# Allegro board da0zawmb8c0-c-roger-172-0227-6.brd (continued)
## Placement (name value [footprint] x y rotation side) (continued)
C6616  180p/50V_4  [C0402]  54.8 103.11 270 top
C6617  *15p/50V_4  [C0402]  66.79 26.48 180 bottom
C6618  0.1u/6.3V_2  [C0201]  172.58 19.95 0 top
C6619  0.1u/6.3V_2  [C0201]  100.9 60.44 180 bottom
C6620  0.1u/6.3V_2  [C0201]  102.98 37.43 90 top
C6622  0.1u/6.3V_2  [C0201]  103.39 30.69 90 bottom
C6623  0.1u/6.3V_2  [C0201]  87.69 49.29 90 top
C6624  0.1u/25V_4  [C0402]  60.03 107.1 0 top
C6625  1000p/50V_4  [C0402]  60.03 106.13 0 top
C6626  *0.1u/16V_2  [C0201]  71.44 32.12 180 bottom
C20000  0.1u/16V_4  [C0402]  45.27 114.54 180 top
C20001  180p/50V_4  [C0402]  56.2 103.82 270 bottom
C20002  180p/50V_4  [C0402]  57.19 104.79 270 bottom
CN1  50281-00201-001  [50281-00201-001-2P-L]  14.3 3.45 180 bottom
CN2  USB3.0 CONN  [UB3-10580-09001-9P]  7.4 54.44 90 bottom
CN3  USB3.0 CONN  [UB3-10580-09001-9P]  7.4 34.44 90 bottom
CN8  2RJ1622-001111F  [RJ45-2RJ1622-001111F-8P]  10.05 96.2 90 bottom
CN10  TPC@USB3.1  [UB31-C12321-1242D-L-24P]  1.46 15.9 90 bottom
CN13  KBL@50505-00401-v01-4p-l  [50505-00401-V01-4P-L]  204.32 10.95 180 bottom
CN14  PBA@196241-08021-3  [196241-08021-3-8P-L]  58.7 18.15 180 bottom
CN15  ODD@132F18-100000-A2-R  [132F18-100000-A2-R-18P-L]  132.6 14.35 180 bottom
CN16  SSD@NASM0-S6701-TSH4  [NGFF-NASM0-S6701-TSH4-KM-SMT]  30.6 4.35 180 bottom
CN17  NASE0-S6701-TS40  [NGFF-NASE0-S6701-TS40-KE-SMT]  188.5 21.88 270 bottom
CN18  FOR15_17@196153-28021-35  [50584-0280N-V02-28P-L]  161.5 18.5 180 bottom
CN19  FOR14@196153-28021-35  [50584-0280N-V02-28P-L]  139.9 23.2 180 bottom
CN24  *51578-00401-V01  [FPC-51578-00401-V01-4P-L]  45.7 8.75 180 bottom
CN29  196538-40041-3  [196538-40041-3-40P-L]  53.6 110.3 0 bottom
CN33  51653-0080N-V02  [196047-08021-3-8P-L]  72.82 18.55 180 bottom
CN35  51619-04001-V04  [51619-04001-V04-40P-L]  216.35 38.15 270 bottom
CN36  51325-00401-001  [51325-00401-001-4P-L]  117.8 17.6 180 bottom
CN37  10444-19001  [HDMI-10591-19001-19P]  3.4 76.2 90 bottom
CN38  *50208-00401-V02  [50208-00401-V02-4P-L]  35.1 118.05 0 bottom
D1  RB500V-40  [D-1_85X1_25-2P-0_95H]  104.48 53.07 90 bottom
D3  1N4148WS  [D-SOD323-1_85X1_25-0_95H]  53.55 103.75 270 top
D4  EV@RB500V-40  [D-SOD323-1_85X1_25-0_95H]  86.85 100.57 0 top
D11  1N4148WS  [D-SOD323-1_85X1_25-0_95H]  193.2 33.41 270 bottom
D12  *RB500V-40  [D-SOD323-1_85X1_25-0_95H]  201.23 23.13 0 bottom
D13  RB500V-40  [D-SOD323-1_85X1_25-0_95H]  201.92 24.98 0 bottom
D14  BAT54AW-L  [SOT23-1_7-65-3P]  23.94 71.49 270 top
D16  TPC@EGA10402V05AH_0.2p  [R0402]  9.97 18.78 90 bottom
D17  TPC@EGA10402V05AH_0.2p  [R0402]  11.62 13.83 0 bottom
D18  TPC@EGA10402V05AH_0.2p  [R0402]  11.36 18.4 0 bottom
D19  TPC@EGA10402V05AH_0.2p  [R0402]  11.62 13.65 0 top
D20  GS@RB500V-40  [D-SOD323-1_85X1_25-0_95H]  57.16 27.95 270 top
D21  GS@RB500V-40  [D-SOD323-1_85X1_25-0_95H]  59.17 27.93 270 top
D22  *TPM@PESD5V0F1BL  [R0402]  130.08 19.47 180 top
D33  VPORT_0603_220K-V05  [R0603]  148.91 17.26 90 top
D34  *AZ5725-01F.R7G  [ESD-1X0_6-2P]  150.56 18.4 90 top
D50  *AZ5725-01F.R7G  [ESD-1X0_6-2P]  15.56 82.79 90 bottom
D51  *RB500V-40  [D-SOD323-1_85X1_25-0_95H]  167.32 27.77 0 top
D60  *RB500V-40  [D-SOD323-1_85X1_25-0_95H]  169.81 30.85 270 top
D61  RB500V-40  [D-SOD323-1_85X1_25-0_95H]  167.32 30.62 0 top
D62  *RB500V-40  [D-SOD323-1_85X1_25-0_95H]  167.32 29.2 0 top
D63  RB500V-40  [D-SOD323-1_85X1_25-0_95H]  174.97 24.67 0 top
D64  *RB500V-40  [D-SOD323-1_85X1_25-0_95H]  167.19 32.04 0 top
D65  TVM0G5R5M220R_22p  [R0402]  182.94 30.09 0 top
D72  BAT54CW  [SOT23-1_7-65-3P]  46.67 25.39 270 top
D2016  *RB500V-40  [D-SOD323-1_85X1_25-0_95H]  167.32 26.38 0 top
D6541  TPC@P4SMAFJ20A  [D-3_8X2_5]  15.05 13.7 270 bottom
D6542  TPC@PDZ5.6B  [D-SOD323-1_7X1_25-PMEG4005AEA]  19.62 10.02 0 top
D6543  1N4148WS  [D-SOD323-1_85X1_25-0_95H]  194.7 33.41 270 bottom
D13081  *PESD5V0H1BSF  [D-0_6X0_3-0_32H-SMT]  17.74 74.78 90 bottom
D13082  *PESD5V0H1BSF  [D-0_6X0_3-0_32H-SMT]  17.74 76.08 270 bottom
D13083  *PESD5V0H1BSF  [D-0_6X0_3-0_32H-SMT]  16.57 76.11 90 bottom
D13084  *PESD5V0H1BSF  [D-0_6X0_3-0_32H-SMT]  16.57 77.41 270 bottom
D13085  *PESD5V0H1BSF  [D-0_6X0_3-0_32H-SMT]  17.74 78.01 90 bottom
D13086  *PESD5V0H1BSF  [D-0_6X0_3-0_32H-SMT]  17.74 79.31 270 bottom
D13087  *PESD5V0H1BSF  [D-0_6X0_3-0_32H-SMT]  16.57 79.82 90 bottom
D13088  *PESD5V0H1BSF  [D-0_6X0_3-0_32H-SMT]  16.57 81.12 270 bottom
D13089  *PESD5V0H1BSF  [D-0_6X0_3-0_32H-SMT]  14.41 82.94 180 top
D13090  *PESD5V0H1BSF  [D-0_6X0_3-0_32H-SMT]  15.71 82.28 180 top
D13091  *VPORT_0603_220K-V05  [R0603]  38.59 122.03 270 bottom
D13092  *VPORT_0603_220K-V05  [R0603]  40.37 120.61 90 bottom
EC1  *220p/50V_4  [C0402]  66.74 41.9 0 bottom
EC2  18p/50V_4  [C0402]  62.8 51.04 0 bottom
EC3  18p/50V_4  [C0402]  64.58 46.6 90 top
EC5  180p/25V_2  [C0201]  60.53 87.4 270 bottom
EC6  180p/25V_2  [C0201]  50.35 57.52 180 top
EC7  *PBA@AZ5725-01F.R7G  [ESD-1X0_6-2P]  57.08 22.52 0 bottom
EC8  *PBA@AZ5725-01F.R7G  [ESD-1X0_6-2P]  59.02 22.52 0 bottom
EC9  SSD@10u/6.3V_4  [C0402_2]  22.29 6.97 0 top
EC10  SSD@10u/6.3V_4  [C0402_2]  24.83 5.45 0 top
EC11  SSD@0.1u/16V_2  [C0201]  24.83 4.43 180 top
EC12  *33p/50V_4  [C0402]  195.06 19.93 270 bottom
EC13  *220p/50V_4  [C0402]  180.38 20.13 90 bottom
EC6500  TPC@22u/6.3V_6  [C0603]  11.24 21.63 270 bottom
FAN3  50278-00401-001  [WTB-50278-00401-V01-4P-L]  171.72 29.5 90 bottom
HD1  51625-01201-001  [51625-01201-001-12P-L]  217.53 13.57 270 bottom
HE1  APX8132AI-TRG  [SOT23-2_38-95-3P]  34.9 122.75 90 top
HOLE2  *h-tic157bc276d150p2  [H-TIC157BC276D150P2]  71.88 89.73 180 bottom
HOLE3  *h-tic157bc276d150p2  [H-TIC157BC276D150P2]  71.88 27.73 180 bottom
HOLE4  *h-tic157bc276d150p2  [H-TIC157BC276D150P2]  106.88 58.74 180 bottom
HOLE5  EV@H-C256I186D102P2  [H-C256I186D102P2]  90.53 123.23 180 bottom
HOLE6  EV@H-C256I186D102P2  [H-C256I186D102P2]  119.53 84.23 180 bottom
HOLE7  *hg-c354i158d118p2  [HG-C354I158D118P2]  17.48 68.15 180 bottom
HOLE8  *hg-c354i274d220p2  [HG-C354I274D220P2]  86.2 15.5 180 bottom
HOLE9  *hg-o335x315d252x232p2  [HG-O335X315D252X232P2]  11.25 109.2 180 bottom
HOLE10  h-davidoff-1  [H-DAVIDOFF-1]  216.8 21.88 180 bottom
HOLE11  *H-DAVIDOFF-1-1  [H-DAVIDOFF-1-1]  5.2 4.4 180 bottom
HOLE12  *h-c98d98n  [H-C98D98N]  142.5 123.5 180 bottom
HOLE13  *h-s157d157n  [H-S157D157N]  110.17 72.38 0 top
HOLE14  *spad-c315np  [SPAD-C315NP]  131.79 64.66 0 top
HOLE15  *spad-c354np  [SPAD-C354NP]  140.49 22.1 0 top
HOLE16  *spad-re209x315np  [SPAD-RE209X315NP]  215.74 37.1 0 top
HOLE17  *spad-c354np  [SPAD-C354NP]  41.2 10 0 top
HOLE18  *spad-davidoff-1  [SPAD-DAVIDOFF-1]  43.94 123.9 0 top
HOLE19  *H-DAVIDOFF-3  [H-DAVIDOFF-3]  136.2 123.5 180 bottom
HOLE20  *HG-C276D126P2  [HG-C276D126P2]  216.55 54 180 bottom
HOLE21  *h-c75d75n  [H-C75D75N]  4.2 24 180 bottom
HOLE22  *SPAD-RE138X197  [SPAD-RE138X197]  3.35 108.2 180 bottom
HOLE23  *h-c98d98n  [2D-BARCODE-6X6-S]  18.76 109.23 0 top
HOLE24  *h-s157d157n  [2D-BARCODE-6X6-S]  18.02 104.15 0 bottom
J9007  *JUMP  [JOPEN25X30_S]  49.59 22.85 180 top
JDIM1  D4AS0-26010-1P40  [DDR4-D4AS0-26001-1P40-STD-SMT]  54.35 62.83 270 bottom
L1  BLM15AG121SN1D  [R0402]  99.63 33.64 0 top
L2  BLM15PG100SN1D  [R0402]  100.85 42.79 270 top
L3  BLM15AG121SN1D  [R0402]  90.21 31.89 270 top
L4  EV@HCB1005KF-330T30  [R0402]  105.6 99.43 0 top
L5  *EV@HCB1608KF_300_2A  [R0603]  89.44 102.14 180 top
L6  EV@HCB1005KF-330T30  [R0402]  89.85 100.93 180 top
L7  EV@HCB1005KF-330T30  [R0402]  88.07 106.29 180 top
L8  EV@HCB1005KF-330T30  [R0402]  88.07 107.3 180 top
L11  BLM15AG121SN1D  [R0402]  202.14 21.17 180 top
L12  BLM15AG601SN1D  [R0402]  41.34 103.62 90 bottom
L13  BLM15AG601SN1D  [R0402]  42.48 103.62 90 bottom
L15  PBY160808T-600Y-N  [R0603]  210.93 27.98 0 bottom
L16  HCB2012KF-220T60  [R0805]  202.75 31.79 0 top
L23  HCB1005KF-330T30  [R0402]  66.99 23.1 270 top
L24  HCB1005KF-330T30  [R0402]  71.89 21.2 270 top
L28  HCB1608KF-121T30  [R0603]  210.75 34.25 0 bottom
L29  BLM15AG121SN1D  [R0402]  201.61 19.77 90 top
L30  BLM15AG121SN1D  [R0402]  185.28 32.24 180 top
NOREF  -  [unnamed]  168.97 17.26 0 top
NOREF#2  -  [unnamed]  23.56 116.19 0 top
NOREF#3  -  [#2]  1.84 -42.94 0 top
NOREF#4  -  [unnamed]  10.35 22.97 0 top
NOREF#5  -  [#2]  166.94 -30.24 0 top
NOREF#6  -  [#2]  107.12 22.34 0 top
NOREF#7  -  [unnamed]  11.36 8.75 180 bottom
NOREF#8  -  [unnamed]  25 116.32 180 bottom
NOREF#9  -  [unnamed]  210.12 43.93 180 bottom
NOREF#10  -  [#2]  30.29 93.33 180 bottom
PC1  1000p/50V_4  [C0402]  44.05 121.73 90 top
PC2  0.047u/50V_6  [C0603]  45.88 121.7 0 top
PC3  0.1u/25V_4  [C0402]  129.02 27.24 270 bottom
PC4  0.1u/25V_4  [C0402]  129.98 27.24 270 bottom
PC5  0.1u/50V_4  [C0402]  40.09 118.81 0 bottom
PC6  0.1u/25V_4  [C0402]  129.35 28.59 180 bottom
PC7  2200p/50V_4  [C0402]  100.54 17.31 90 top
PC8  0.01u/50V_4  [C0402]  133.68 27.7 90 top
PC9  2.2u/10V_4  [C0402]  131.99 29.73 180 top
PC10  *47p/50V_4  [C0402]  107.63 15.87 270 top
PC11  *47p/50V_4  [C0402]  100.52 15.11 270 top
PC12  0.1u/50V_4  [C0402]  101.92 17.26 90 top
PC13  2200p/50V_4  [C0402]  12.41 118.43 90 top
PC14  0.1u/50V_4  [C0402]  40.09 117.84 0 bottom
PC15  0.047u/50V_6  [C0603]  129.78 31.23 0 bottom
PC16  0.47u/25V_6  [C0603]  129.93 33.06 0 bottom
PC17  *0.01u/50V_4  [C0402]  120.46 26.66 270 top
PC18  *100p/50V_4  [C0402]  136.46 30.72 180 top
PC19  *680p/50V_6  [C0603]  127.6 28.31 270 bottom
PC20  100p/50V_4  [C0402]  136.46 32.75 180 top
PC25  0.1u/50V_4  [C0402]  132.12 33.21 0 bottom
PC35  0.1u/50V_4  [C0402]  132.6 32.14 90 top
PC36  0.1u/50V_4  [C0402]  133.56 32.14 270 top
PC37  100p/50V_4  [C0402]  137.98 33.49 0 bottom
PC51  2200p/50V_4  [C0402]  24.06 35.42 270 top
PC81  *0.1u/25V_4  [C0402]  122.62 29.2 90 top
PC82  *680p/50V_6  [C0603]  114.74 33.91 270 top
PC83  22u/6.3V_6  [C0603]  114.01 44.69 90 top
PC152  *2200p/50V_4  [C0402]  116.65 33.64 0 top
PC162  *330u/2V_7343H1.9  [CC7343]  64.35 88.43 270 bottom
PC164  22u/25V_8  [C0805]  111.57 29.96 180 bottom
PC165  2200p/50V_4  [C0402]  111.01 33.46 180 bottom
PC166  22u/25V_8  [C0805]  111.57 31.96 180 bottom
PC167  0.1u/50V_4  [C0402]  94.12 24.12 180 bottom
PC168  *100p/50V_4  [C0402]  94.12 23.09 0 bottom
PC170  10u/25V_8  [C0805]  127.39 32.19 90 bottom
PC172  2200p/50V_4  [C0402]  126.83 31.33 90 top
PC185  *1u/25V_4  [C0402]  34.35 22.85 270 top
PC188  *0.1u/6.3V_2  [C0201]  33.01 23.23 270 top
PC217  10u/25V_8  [C0805]  118.43 33.64 0 bottom
PC218  2200p/50V_4  [C0402]  125.36 29.93 180 top
PC219  *22u/6.3V_6  [C0603]  109.23 33.9 90 bottom
PC220  22u/6.3V_6  [C0603]  112.69 34.12 180 top
PC221  *0.01u/50V_4  [C0402]  120.94 34.07 180 bottom
PC222  22u/6.3V_6  [C0603]  107.81 33.9 90 bottom
PC224  22u/6.3V_6  [C0603]  112.69 36.97 180 top
PC225  *1000p/50V_4  [C0402]  121.93 36.03 180 bottom
PC227  22u/6.3V_6  [C0603]  106.39 33.9 90 bottom
PC228  *0.047u/6.3V_2  [C0201]  121.32 40.47 0 bottom
PC229  10u/6.3V_6  [C0603]  167.83 23 90 top
PC230  22u/6.3V_6  [C0603]  112.69 38.39 180 top
PC231  *22u/6.3V_6  [C0603]  112.69 35.55 180 top
PC232  0.047u/6.3V_2  [C0201]  119.04 41.39 90 bottom
PC233  0.1u/16V_4  [C0402]  112.53 39.58 180 top
PC234  10u/6.3V_6  [C0603]  117.26 41.74 0 bottom
PC235  0.1u/25V_4  [C0402]  114.84 40.3 180 top
PC236  *22u/6.3V_6  [C0603]  103.31 40.83 180 top
PC242  4.7u/6.3V_4  [C0402_2]  159.32 23.23 270 bottom
PC267  *150p/50V_4  [C0402]  67.78 123.28 180 top
PC268  1u/6.3V_4  [C0402]  61.15 125.46 180 top
PC276  *0.1u/16V_4  [C0402]  63.99 124.57 270 top
PC280  0.1u/16V_4  [C0402]  68.59 122.67 90 bottom
PC283  *0.1u/16V_4  [C0402]  67.5 124.7 180 top
PC285  *1u/6.3V_4  [C0402]  68.01 117.74 0 top
PC288  10u/25V_8  [C0805]  62.09 119.49 0 bottom
PC289  10u/25V_8  [C0805]  62.22 121.5 0 bottom
PC290  0.1u/25V_4  [C0402]  66.99 116.32 270 bottom
PC292  2200p/50V_4  [C0402]  66.71 114.72 0 bottom
PC293  *0.1u/16V_4  [C0402]  52.28 125.03 270 top
PC294  22u/6.3V_8  [C0805]  52 123.4 270 bottom
PC295  22u/6.3V_8  [C0805]  49.06 121.86 0 top
PC296  22u/6.3V_8  [C0805]  54.19 123.4 270 bottom
PC297  22u/6.3V_8  [C0805]  49.06 121.86 0 bottom
PC298  0.033u/10V_4  [C0402]  68.03 121.32 180 bottom
PC299  10u/6.3V_6  [C0603]  68.16 119.54 90 top
PC300  *2200p/50V_4  [C0402]  60.26 116.45 0 top
PC301  0.1u/25V_4  [C0402]  63.71 116.24 270 top
PC302  10u/6.3V_6  [C0603]  64.81 124.57 180 bottom
PC304  10u/6.3V_6  [C0603]  67.45 124.7 180 bottom
PC305  *22u/6.3V_8  [C0805]  56.37 123.4 270 bottom
PC306  *22u/6.3V_8  [C0805]  57.03 120.61 180 bottom
PC423  *0.1u/6.3V_2  [C0201]  136.79 60.08 90 bottom
PC551  *2200p/50V_6  [C0603]  37.15 32.24 270 top
PC561  0.1u/6.3V_2  [C0201]  37.02 27.42 270 top
PC562  22u/6.3V_6  [C0603]  35.11 26.91 90 top
PC563  22u/6.3V_6  [C0603]  33.72 30.47 270 top
PC571  10u/6.3V_4  [C0402_2]  44.38 29.2 180 top
PC572  0.01u/50V_4  [C0402]  44.38 28.05 180 top
PC574  *22p/50V_4  [C0402]  39.18 25.92 270 top
PC581  *0.1u/6.3V_2  [C0201]  39.18 27.55 0 top
PC756  *0.1u/16V_4  [C0402]  138.64 31.66 270 bottom
PC6000  0.1u/25V_4  [C0402]  142.43 30.59 90 bottom
PC6001  0.1u/25V_4  [C0402]  148.02 35.42 90 bottom
PC6002  2200p/50V_4  [C0402]  142.94 37.32 90 bottom
PC6003  0.1u/25V_4  [C0402]  141.41 30.59 270 bottom
PC6004  10u/25V_8  [C0805]  141.06 32.5 0 bottom
PC6005  10u/25V_8  [C0805]  140.65 34.48 0 bottom
PC6006  *680p/50V_6  [C0603]  143.57 28.92 0 bottom
PC6007  0.1u/16V_4  [C0402]  144.71 31.41 270 top
PC6008  22u/6.3V_6  [C0603]  156.48 35.95 270 bottom
PC6009  22u/6.3V_6  [C0603]  157.9 35.95 270 bottom
PC6010  22u/6.3V_6  [C0603]  156.48 35.98 270 top
PC6011  *22u/6.3V_6  [C0603]  157.9 35.95 270 top
PC6012  *22u/6.3V_6  [C0603]  159.95 35.42 180 top
PC6013  0.1u/16V_4  [C0402]  157.67 33.57 180 top
PC6014  22u/6.3V_6  [C0603]  159.93 35.39 180 bottom
PC6015  1u/25V_4  [C0402]  158.05 28.18 180 top
PC6016  1u/25V_4  [C0402]  152.67 27.82 90 top
PC6017  0.1u/16V_4  [C0402]  145.73 31.41 270 top
PC6018  10u/6.3V_6  [C0603]  157.8 23.05 90 top
PC6019  0.1u/16V_4  [C0402]  156.42 22.67 90 top
PC6020  0.1u/16V_4  [C0402]  153.45 22.64 90 top
PC6021  10u/6.3V_6  [C0603]  152.26 22.47 90 top
PC6022  1u/10V_4  [C0402]  144.51 34.43 0 bottom
PC6023  4.7u/6.3V_4  [C0402_2]  145.88 37.12 180 top
PC6024  10p/50V_4  [C0402]  147.56 35.34 90 top
PC6025  0.1u/16V_4  [C0402]  155.31 27.49 90 bottom
PC6026  *0.1u/16V_4  [C0402]  156.27 27.49 90 bottom
PC6027  *0.1u/16V_4  [C0402]  153.38 27.49 90 bottom
PC6028  1000p/50V_4  [C0402]  155.46 22.64 90 top
PC6029  1000p/50V_4  [C0402]  154.42 22.64 90 top
PC6030  0.1u/25V_4  [C0402]  49.21 17 90 bottom
PC6031  0.1u/25V_4  [C0402]  46.8 20.18 90 bottom
PC6032  10u/25V_8  [C0805]  52.67 15.73 90 bottom
PC6033  10u/25V_8  [C0805]  50.68 15.73 90 bottom
PC6034  2200p/50V_4  [C0402]  48.25 17 270 bottom
PC6035  0.1u/25V_4  [C0402]  39.18 18.91 270 top
PC6036  1u/25V_4  [C0402]  25.23 25.67 180 top
PC6037  1u/25V_4  [C0402]  22.59 30.75 270 top
PC6038  *680p/50V_6  [C0603]  42.73 20.56 180 top
PC6039  0.1u/16V_4  [C0402]  47.64 13.3 180 bottom
PC6040  10u/6.3V_6  [C0603]  17.99 25.18 0 top
PC6041  0.1u/16V_4  [C0402]  20.81 22.67 90 top
PC6042  0.1u/16V_4  [C0402]  18.98 31.71 270 top
PC6043  10u/6.3V_6  [C0603]  20.79 30.92 180 top
PC6044  22u/6.3V_6  [C0603]  39.58 15.99 90 top
PC6045  22u/6.3V_6  [C0603]  34.99 15.99 90 top
PC6046  22u/6.3V_6  [C0603]  35.88 15.1 180 bottom
PC6047  22u/6.3V_6  [C0603]  38.16 15.99 90 top
PC6048  *22u/6.3V_6  [C0603]  41.06 15.96 90 top
PC6049  *22u/6.3V_6  [C0603]  36.49 15.99 90 top
PC6050  0.1u/16V_4  [C0402]  33.46 15.1 0 bottom
PC6051  0.1u/16V_4  [C0402]  25.23 27.6 180 top
PC6052  *0.1u/16V_4  [C0402]  25.23 26.63 180 top
PC6053  *0.1u/16V_4  [C0402]  25.23 28.56 180 top
PC6054  4.7u/10V_6  [C0603]  44 18.02 270 top
PC6055  0.1u/16V_4  [C0402]  42.56 15.68 180 bottom
PC6056  1000p/50V_4  [C0402]  19.37 26.76 0 top
PC6057  1000p/50V_4  [C0402]  19.37 27.75 0 top
PC6058  1u/10V_4  [C0402]  42.61 16.67 0 bottom
PC6059  10p/50V_4  [C0402]  44.38 14.39 180 bottom
PC6228  0.1u/16V_4  [C0402]  103.31 26.63 90 bottom
PC6229  0.47u/6.3V_4  [C0402]  166.64 23.89 270 top
PC6230  10u/6.3V_6  [C0603]  169.99 22.72 180 bottom
PC6231  0.1u/16V_4  [C0402]  168.13 22.57 90 bottom
PC7000  0.22u/25V_4  [C0402]  135.52 51.57 0 top
PC7001  1000p/50V_4  [C0402]  138.97 57.54 0 top
PC7003  *0.1u/6.3V_2  [C0201]  140.32 57.54 90 top
PC7004  0.47u/6.3V_2  [C0201]  144.18 57.75 0 top
PC7005  *0.1u/6.3V_2  [C0201]  141.21 61.43 180 bottom
PC7006  *0.1u/6.3V_2  [C0201]  141.92 52.56 180 top
PC7007  *100p/50V_4  [C0402]  144.33 52.59 0 top
PC7008  *100p/50V_4  [C0402]  145.73 51.8 270 top
PC7009  *100p/50V_4  [C0402]  144.33 51.29 0 top
PC7010  330p/16V_2  [C0201]  144 46.42 0 bottom
PC7011  82p/50V_4  [C0402]  143.09 48.25 180 bottom
PC7012  *68p/50V_4  [C0402]  144.82 48.25 180 bottom
PC7013  *100p/50V_4  [C0402]  137.63 57.67 90 top
PC7014  *100p/50V_4  [C0402]  135.19 58.53 270 top
PC7015  *100p/50V_4  [C0402]  136.66 57.64 90 top
PC7016  270p/50V_4  [C0402]  133.14 56.11 0 bottom
PC7017  82p/50V_4  [C0402]  133.64 58.43 90 bottom
PC7018  *68p/50V_4  [C0402]  133.15 54.17 180 bottom
PC7019  *100p/50V_4  [C0402]  144.21 51.68 0 bottom
PC7020  560p/50V_4  [C0402]  146.67 50.66 0 bottom
PC7021  68p/50V_4  [C0402]  144.32 54.5 180 bottom
PC7022  *100p/50V_4  [C0402]  144.92 53.07 90 bottom
PC7023  *68p/50V_4  [C0402]  144.59 55.61 270 top
PC7024  *100p/50V_4  [C0402]  143.67 53.07 90 bottom
PC7025  0.1u/6.3V_2  [C0201]  141.18 49.34 180 bottom
PC7026  4.7u/6.3V_4  [C0402]  135.53 52.56 180 top
PC7027  0.1u/6.3V_2  [C0201]  141.92 46.42 180 bottom
PC7029  0.1u/6.3V_2  [C0201]  141.67 54.34 0 top
PC7030  0.1u/6.3V_2  [C0201]  135.06 60.87 270 bottom
PC7031  10u/25V_8  [C0805]  131 69.07 90 bottom
PC7032  10u/25V_8  [C0805]  128.43 73.67 270 bottom
PC7033  *10u/25V_8  [C0805]  130.64 73.67 270 bottom
PC7034  0.1u/25V_4  [C0402]  130.95 69.66 90 top
PC7035  2200p/50V_4  [C0402]  131.91 69.66 270 top
PC7036  *15u/25V_3528H1.9  [C3528]  51.57 19.95 270 bottom
PC7037  10u/25V_8  [C0805]  123.48 69.3 90 bottom
PC7038  0.1u/25V_4  [C0402]  132.9 69.66 90 top
PC7039  *0.1u/16V_4  [C0402]  116.17 57.44 0 top
PC7040  22u/6.3V_8  [C0805]  109.99 67.75 270 bottom
PC7041  22u/6.3V_8  [C0805]  111.97 67.75 270 bottom
PC7042  *22u/6.3V_8  [C0805]  115.12 61.73 180 bottom
PC7043  *22u/6.3V_8  [C0805]  113.96 67.75 270 bottom
PC7044  *330u/2V_7343H1.9  [CC7343]  119.24 51.17 270 bottom
PC7045  330u/2V_7343H1.9  [CC7343]  119.19 61.76 90 bottom
PC7046  *2200p/50V_4  [C0402]  130.85 65.34 180 bottom
PC7047  0.47u/6.3V_4  [C0402]  137.22 49.59 90 bottom
PC7049  U42@10u/25V_8  [C0805]  123.12 47.81 270 bottom
PC7050  U42@10u/25V_8  [C0805]  122.49 45.2 0 bottom
PC7051  U42@10u/25V_8  [C0805]  130.87 48.17 270 bottom
PC7052  *U42@10u/25V_8  [C0805]  130.87 44.36 90 bottom
PC7053  U42@0.1u/25V_4  [C0402]  126.66 44.05 90 bottom
PC7054  U42@2200p/50V_4  [C0402]  125.69 44.05 270 bottom
PC7055  U42@0.1u/25V_4  [C0402]  124.7 44.05 90 bottom
PC7056  U42@0.22u/25V_6  [C0603]  133.18 44.82 0 bottom
PC7057  U42@0.1u/16V_4  [C0402]  107.12 50.41 270 bottom
PC7058  U42@22u/6.3V_8  [C0805]  108.77 49.9 90 bottom
PC7059  U42@22u/6.3V_8  [C0805]  115.15 57.69 180 bottom
PC7060  U42@22u/6.3V_8  [C0805]  110.93 49.9 90 bottom
PC7061  U42@22u/6.3V_8  [C0805]  115.12 59.73 180 bottom
PC7062  U42@330u/2V_7343H1.9  [CC7343]  114.51 51.17 270 bottom
PC7063  U42@1u/6.3V_4  [C0402]  134.81 49.67 90 bottom
PC7064  *U42@2200p/50V_4  [C0402]  131.38 51.07 270 bottom
PC7065  U42@0.47u/6.3V_4  [C0402]  139.58 47.71 90 bottom
PC7066  10u/25V_8  [C0805]  139.33 37.1 270 bottom
PC7067  10u/25V_8  [C0805]  141.44 37.1 270 bottom
PC7068  0.1u/25V_4  [C0402]  141.41 38.09 270 top
PC7069  2200p/50V_4  [C0402]  139.51 38.14 90 top
PC7070  0.1u/25V_4  [C0402]  135.82 40.88 180 top
PC7072  22u/6.3V_8  [C0805]  115.38 44.72 270 bottom
PC7073  22u/6.3V_8  [C0805]  113.4 44.64 270 bottom
PC7074  *22u/6.3V_8  [C0805]  124.45 42.2 180 bottom
PC7075  *22u/6.3V_8  [C0805]  119.85 44.69 270 bottom
PC7076  *22u/6.3V_8  [C0805]  124.19 36.69 90 bottom
PC7077  *22u/6.3V_8  [C0805]  117.66 44.69 270 bottom
PC7078  *2200p/50V_4  [C0402]  138.57 43.62 0 bottom
PC7079  0.47u/6.3V_4  [C0402]  141.97 56.15 180 top
PC7080  10u/25V_8  [C0805]  124.47 78.4 315 bottom
PC7081  10u/25V_8  [C0805]  116.64 72.79 315 bottom
PC7082  10u/25V_8  [C0805]  121.45 70.27 90 bottom
PC7083  *10u/25V_8  [C0805]  119.14 73.16 315 bottom
PC7084  0.1u/25V_4  [C0402]  124.04 78.19 315 top
PC7085  2200p/50V_4  [C0402]  124.75 78.95 135 top
PC7086  0.1u/25V_4  [C0402]  123.28 79.44 225 top
PC7087  *0.1u/16V_4  [C0402]  93.86 78.55 90 top
PC7088  22u/6.3V_8  [C0805]  78.27 87.13 0 bottom
PC7089  22u/6.3V_8  [C0805]  77.86 89.11 0 bottom
PC7090  *22u/6.3V_8  [C0805]  77.48 93.94 0 bottom
PC7091  *22u/6.3V_8  [C0805]  101.15 80.38 90 bottom
PC7092  *22u/6.3V_8  [C0805]  79.16 85.15 0 bottom
PC7093  *22u/6.3V_8  [C0805]  81.47 93.84 180 bottom
PC7094  330u/2V_7343H1.9  [CC7343]  104.79 78.65 270 bottom
PC7095  *330u/2V_7343H1.9  [CC7343]  108.01 85.97 0 bottom
PC7096  *2200p/50V_4  [C0402]  115.61 74.76 45 bottom
PC7097  0.47u/6.3V_4  [C0402]  133.41 58.89 0 top
PC7099  0.1u/25V_4  [C0402]  141.97 55.18 180 top
PC7100  *1000p/25V_4  [C0402]  133.41 57.92 0 top
PC7101  0.22u/25V_6  [C0603]  127.7 76.29 0 top
PC7102  1u/6.3V_4  [C0402]  129.7 78.55 270 bottom
PC7103  0.22u/25V_6  [C0603]  140.78 40.96 0 top
PC7104  1u/6.3V_4  [C0402]  143.44 43.19 270 bottom
PC7105  0.22u/25V_6  [C0603]  118.78 70.29 180 top
PC7106  1u/6.3V_4  [C0402]  116.98 68.11 90 bottom
PC9000  EV@2.2u/10V_4  [C0402]  79.06 111.11 270 top
PC9001  EV@10u/25V_8  [C0805]  73.34 120.51 180 top
PC9002  *EV@10u/25V_8  [C0805]  73.34 124.57 180 top
PC9003  EV@0.1u/25V_4  [C0402]  70.37 124.88 270 bottom
PC9004  EV@1u/25V_6  [C0603]  68.41 115.61 270 top
PC9005  EV@10u/25V_8  [C0805]  73.34 122.54 180 top
PC9006  EV@2200p/50V_4  [C0402]  69.35 124.88 270 bottom
PC9007  *EV@15u/25V_3528H1.9  [C3528]  73.47 124.07 180 bottom
PC9008  EV@0.22u/25V_6  [C0603]  77.61 113.55 270 top
PC9009  EV@22u/6.3V_8  [C0805]  87.69 117.72 180 bottom
PC9010  EV@330u/2V_7343H1.9  [CC7343]  80.48 121.42 180 top
PC9011  EV@330u/2V_7343H1.9  [CC7343]  110.25 123.56 180 bottom
PC9012  *EV@2200p/50V_4  [C0402]  75.25 118.1 0 top
PC9013  EV@0.22u/10V_4  [C0402]  73.24 115.43 270 top
PC9014  *EV@0.22u/10V_4  [C0402]  72.07 106.67 270 top
PC9015  EV@10u/25V_8  [C0805]  81.49 101.46 90 bottom
PC9016  EV@10u/25V_8  [C0805]  79.51 101.46 90 bottom
PC9017  *EV@10u/25V_8  [C0805]  83.48 101.46 90 bottom
PC9018  EV@0.1u/25V_4  [C0402]  78.5 106.01 270 bottom
PC9019  EV@2200p/50V_4  [C0402]  77.51 106.01 270 bottom
PC9020  EV@0.22u/25V_6  [C0603]  77.91 108.44 90 top
PC9021  EV@330u/2V_7343H1.9  [CC7343]  86.88 104.53 270 bottom
PC9022  EV@22u/6.3V_8  [C0805]  103.85 120.86 0 bottom
PC9023  EV@0.1u/16V_4  [C0402]  71.69 111.21 180 bottom
PC9024  *EV@2200p/50V_4  [C0402]  82.87 106.59 0 top
PC9025  EV@4700p/25V_4  [C0402]  74.48 112.66 90 bottom
PC9026  EV@1500p/50V_4  [C0402]  71.56 113.83 270 bottom
PC9027  EV@56p/50V_4  [C0402]  69.23 109.97 0 top
PC9028  *EV@100p/50V_4  [C0402]  70.65 110.45 270 top
PC9029  EV@56p/50V_4  [C0402]  69.23 110.93 0 top
PC9030  *EV@56p/50V_4  [C0402]  73.37 108.62 270 bottom
PC9053  EV@1u/25V_4  [C0402]  21.14 90.16 90 top
PC9054  EV@1u/25V_4  [C0402]  25.72 91.3 180 top
PC9055  EV@10u/6.3V_6  [C0603]  20.64 97.9 0 top
PC9056  EV@0.1u/16V_4  [C0402]  20.76 96.63 0 top
PC9057  EV@0.1u/16V_4  [C0402]  25.33 93.84 180 top
PC9058  EV@10u/6.3V_6  [C0603]  25.59 95.11 180 top
PC9059  EV@0.1u/16V_4  [C0402]  23.18 90.16 90 top
PC9060  EV@0.1u/16V_4  [C0402]  24.19 90.16 90 top
PC9062  EV@1000p/50V_4  [C0402]  22.54 96.63 270 top
PC9063  EV@1000p/50V_4  [C0402]  23.56 96.63 270 top
PC9064  *EV@820p/50V_4  [C0402]  22.16 90.16 90 top
PC9065  EV@0.1u/16V_4  [C0402]  65.85 95.49 270 bottom
PC9066  EV@10u/6.3V_6  [C0603]  64.58 94.98 270 bottom
PC9067  EV@10u/6.3V_6  [C0603]  69.66 98.61 0 bottom
PC9068  EV@10u/6.3V_6  [C0603]  69.66 100.04 0 bottom
PC9069  EV@0.1u/16V_4  [C0402]  71.94 99.43 180 bottom
PC9071  EV@0.01u/50V_4  [C0402]  74.86 94.22 180 bottom
PC9072  EV@0.1u/16V_4  [C0402]  75.17 102.35 180 bottom
PC9073  *EV@0.1u/16V_4  [C0402]  75.37 95.87 90 bottom
PC9074  *EV@0.01u/50V_4  [C0402]  139.69 62.11 180 bottom
PC9075  EV@10u/6.3V_6  [C0603]  141.59 72.07 180 bottom
PC9076  *EV@0.1u/25V_4  [C0402]  138.87 67.3 180 top
PC9077  EV@2200p/50V_4  [C0402]  139.84 64.04 180 top
PC9078  EV@10u/25V_8  [C0805]  137.07 62.85 0 bottom
PC9079  EV@0.1u/25V_4  [C0402]  137.96 70.34 180 bottom
PC9080  EV@22u/6.3V_6  [C0603]  142.1 74.38 90 bottom
PC9081  EV@22u/6.3V_6  [C0603]  139.23 74.36 90 bottom
PC9082  EV@22u/6.3V_6  [C0603]  142.1 74.38 90 top
PC9083  EV@22u/6.3V_6  [C0603]  140.65 74.38 90 top
PC9084  EV@22u/6.3V_6  [C0603]  139.23 74.36 90 top
PC9085  *EV@22u/6.3V_6  [C0603]  138.82 77.58 0 top
PC9086  *EV@22u/6.3V_6  [C0603]  140.65 74.38 90 bottom
PC9087  EV@0.1u/16V_4  [C0402]  138.01 74.38 90 top
PC9088  *EV@680p/50V_6  [C0603]  133.69 67.55 180 bottom
PC9089  *EV@1000p/50V_4  [C0402]  141.46 64.88 180 bottom
PC9090  EV@0.22u/10V_4  [C0402]  141.87 67.96 180 bottom
PC9091  EV@0.01u/6.3V_2  [C0201]  140.98 69.46 0 bottom
PC9092  *10u/6.3V_4  [C0402_2]  33.59 25.26 270 top
PC9093  *0.1u/6.3V_2  [C0201]  31.96 24.55 270 top
PC9094  *0.1u/6.3V_2  [C0201]  22.87 23.35 180 top
PC9095  *10u/6.3V_4  [C0402_2]  25.59 22.21 90 top
PC9096  *10u/6.3V_4  [C0402_2]  24.32 22.21 90 top
PC9097  *22p/50V_4  [C0402]  159.35 25.9 90 top
PC9098  *22u/6.3V_6  [C0603]  35.27 30.47 270 top
PD2  P4SMAFJ20A  [D-3_8X2_5]  16.06 115.3 180 top
PD3  PDZ5.6B  [D-SOD323-1_7X1_25-PMEG4005AEA]  109.03 16.58 90 top
PD4  PDZ5.6B  [D-SOD323-1_7X1_25-PMEG4005AEA]  99.25 15.82 90 top
PD9000  *EV@RB500V-40  [D-SOD323-1_85X1_25-0_95H]  76.64 115.66 180 top
PD9001  EV@1SS355  [D-SOD323-1_85X1_25-0_95H]  73.09 96.13 90 bottom
PJ1  50458-00801-V02  [50458-00801-V02-8P-L]  102.45 16.42 180 bottom
PJ2  30706-00042-001  [DCJK-30706-00042-001-3P-SMT]  1.85 116.6 90 bottom
PJ3005  *short3720  [SHORT3720]  107.94 35.44 0 top
PJ3008  *short3720  [SHORT3720]  171.21 24.75 90 top
PJ6001  *short3720  [SHORT3720]  154.37 31.1 180 top
PJ6003  *short3720  [SHORT3720]  32.45 18.53 90 top
PJ7001  *short3720  [SHORT3720]  49.85 118.35 180 bottom
PJ9002  *short3720  [SHORT3720]  140.65 78.6 180 bottom
PJ9003  *short3720  [SHORT3720]  70.39 102.98 270 bottom
PJ9005  *short3720  [SHORT3720]  31.05 29.96 270 top
PL5  6.8uH/4.5A_7x7x3  [L6_6X6_6-2_8H]  117.82 29.07 180 bottom
PL12  0.68uH/15.5A_7x7x3  [CHOKE-PCMC063T-3R3MN-SMT]  109.92 38.72 180 bottom
PL14  2.2uH/1.67A_2.5x2.0x1.2  [L2_5X2-1_2H]  166.05 22.97 0 bottom
PL30  1uH/11A_7x7x3  [L6_6X6_6-2_8H]  56.6 121.86 180 top
PL551  1uH/3.35A_2.5x2.0x1.2  [L2_5X2-1_2H]  37.6 29.58 180 top
PL6000  1uH/11A_7x7x3  [L6_6X6_6-2_8H]  152.21 32.12 0 bottom
PL6001  1uH/11A_7x7x3  [L6_6X6_6-2_8H]  37.07 19.42 180 bottom
PL7000  0.15uH/37A_7x7x3  [CHOKE-PCMC063T-3R3MN-SMT]  126.1 62.14 180 bottom
PL7001  U42@0.15uH/37A_7x7x3  [CHOKE-PCMC063T-3R3MN-SMT]  126.1 54.83 180 bottom
PL7002  0.47uH/17.5A_7x7x3  [CHOKE-PCMC063T-3R3MN-SMT]  129.7 38.87 180 bottom
PL7003  0.15uH/37A_7x7x3  [CHOKE-PCMC063T-3R3MN-SMT]  112 79.03 180 bottom
PL9000  EV@0.22uH/23A_7x7x3  [CHOKE-PCMC063T-3R3MN-SMT]  84.62 113.14 0 bottom
PL9001  EV@0.22uH/23A_7x7x3  [CHOKE-PCMC063T-3R3MN-SMT]  81.55 120.13 0 bottom
PL9002  EV@0.68uH/15.5A_7x7x3  [CHOKE-PCMC063T-3R3MN-SMT]  135.04 74.43 90 bottom
PQ1  AONS32314  [POWER-5_2X5_55-1_27-5P]  40.12 119.49 0 top
PQ2  AONS32314  [POWER-5_2X5_55-1_27-5P]  117.11 29.2 270 top
PQ6  2N7002K  [SOT23-2-95-3P]  26.35 34.53 0 top
PQ7  DDTC144EUA-7-F  [SOT23-1_7-65-3P]  108.24 43.45 0 bottom
PQ9  AO3404  [SOT23-2_38-95-3P]  26.86 30.95 180 top
PQ10  2N7002K  [SOT23-2-95-3P]  108.39 46.52 180 bottom
PQ11  AO3404  [SOT23-2_38-95-3P]  111.09 42.23 0 top
PQ12  *2N7002K  [SOT23-2-95-3P]  19.49 38.59 90 bottom
PQ14  2N7002K  [SOT23-2-95-3P]  19.11 31.89 90 bottom
PQ16  DDTC144EUA-7-F  [SOT23-1_7-65-3P]  27.37 40.68 90 top
PQ17  2N7002KW  [SOT23-1_7-65-3P]  136.92 35.43 180 top
PQ19  *2N7002K  [SOT23-2-95-3P]  19.11 28.56 90 bottom
PQ25  2N7002K  [SOT23-2-95-3P]  116.67 36.42 90 top
PQ29  AON7410  [DFN-8L-3X3-65-5P-0_9H]  124.65 28.94 0 bottom
PQ30  AON7410  [DFN-8L-3X3-65-5P-0_9H]  124.32 32.85 270 bottom
PQ35  AON7408  [DFN-8L-3X3-65-5P-0_9H]  107.12 39.74 180 top
PQ6000  2N7002K  [SOT23-2-95-3P]  142.3 29.32 270 top
PQ6001  2N7002K  [SOT23-2-95-3P]  46.67 14.97 180 top
PQ7000  AOE6932  [POWER-5X6-1_27-10P]  127.24 68.79 0 bottom
PQ7001  U42@AOE6932  [POWER-5X6-1_27-10P]  127.14 48.16 180 bottom
PQ7002  AON7410  [DFN-8L-3X3-65-5P-0_9H]  136.33 37.07 90 bottom
PQ7003  AON7752  [DFN-8L-3X3-65-5P-0_9H]  136.36 41.01 0 bottom
PQ7004  AOE6936  [POWER-5X6-1_27-10P]  121.52 76.11 225 bottom
PQ9000  EV@AOE6936  [POWER-5X6-1_27-10P]  73.77 119.19 90 bottom
PQ9001  EV@AOE6936  [POWER-5X6-1_27-10P]  81.77 106.41 180 bottom
PQ9008  EV@AON7408  [DFN-8L-3X3-65-5P-0_9H]  69.71 96 0 bottom
PQ9009  EV@2N7002K  [SOT23-2-95-3P]  74.51 104.68 270 bottom
PQ9010  EV@DMG1012T-7  [SOT23-1_38-5-3P]  77.38 103.87 270 bottom
PQ9011  EV@2N7002K  [SOT23-2-95-3P]  71.05 106.97 0 bottom
PQ9050  2N7002K  [SOT23-2-95-3P]  19.49 35.22 90 bottom
PQ9054  AONS32314  [POWER-5_2X5_55-1_27-5P]  46.98 118.05 180 top
PQ9083  EV@LTC044EUBFS8TL  [SOT23-1_7-65-3P]  122.87 122.8 0 top
PQ9084  EV@2N7002KW  [SOT23-1_7-65-3P]  123.76 119.87 90 top
PQ9085  EV@2N7002K  [SOT23-2-95-3P]  135.8 77.91 180 top
PQ9086  EV@DMG1012T-7  [SOT23-1_38-5-3P]  131.91 77.13 270 top
PR1  *Short_0201  [S0201]  51.5 113.78 270 top
PR2  *Short_0201  [S0201]  52.26 113.78 270 top
PR3  0.01_1%_0612  [RC3216]  51.93 116.32 90 top
PR4  *Short_0603  [S0603]  130.87 27.16 180 top
PR5  *Short_0201  [S0201]  131.23 27.47 180 bottom
PR6  *Short_0201  [S0201]  131.23 26.71 180 bottom
PR7  10_1%_6  [R0603]  130.87 25.13 180 top
PR8  *Short_0201  [S0201]  136.74 28.76 90 top
PR9  10K_5%_4  [R0402]  137.27 27.16 90 bottom
PR10  *0_5%_2  [R0201]  99.25 20.94 180 top
PR11  *Short_0603  [S0603]  129.78 29.81 0 bottom
PR12  100_5%_4  [R0402]  102.03 14.72 0 top
PR13  100_5%_4  [R0402]  106.11 15.85 90 top
PR14  100_5%_4  [R0402]  100.65 20.81 0 top
PR15  *10K_5%_4  [R0402]  138.24 27.16 90 bottom
PR16  20_5%_12  [R1206]  129.86 31.48 270 top
PR17  *Short_0201  [S0201]  138.31 29.3 180 bottom
PR18  1M_5%_4  [R0402]  137.98 28.05 180 top
PR19  *Short_0201  [S0201]  138.31 30.01 180 bottom
PR22  *100K_1%_2  [R0201]  137.6 30.9 0 bottom
PR23  SP@41.2K_1%_4  [R0402]  136.46 31.69 0 top
PR25  *Short_0201  [S0201]  137.58 31.61 180 bottom
PR26  *Short_0201  [S0201]  137.3 32.47 270 bottom
PR28  4.02K_1%_4  [R0402]  133.74 33.79 90 bottom
PR29  4.02K_1%_4  [R0402]  134.71 33.87 90 bottom
PR30  *Short_0201  [S0201]  134.55 32.24 0 top
PR31  866K_1%_4  [R0402]  135.67 33.98 90 bottom
PR32  *Short_0201  [S0201]  136.43 32.76 180 bottom
PR33  *4.7_5%_6  [R0603]  123.76 26.33 180 bottom
PR39  100K_1%_4  [R0402]  134.71 33.87 90 top
PR40  100K_1%_4  [R0402]  133.74 33.87 270 top
PR59  1M_5%_6  [R0603]  27.09 37.71 90 top
PR79  1M_5%_6  [R0603]  111.09 42.86 0 bottom
PR80  1M_5%_6  [R0603]  111.44 46.6 270 bottom
PR98  *0_5%_2  [R0201]  121.32 39.76 0 bottom
PR99  *4.7_5%_6  [R0603]  114.77 33.97 90 bottom
PR104  10_5%_6  [R0603]  117.03 38.95 180 top
PR105  22_5%_8  [R0805]  111.85 47.08 0 top
PR106  *22_5%_8  [R0805]  22.29 38.85 90 bottom
PR111  22_5%_8  [R0805]  21.91 32.24 90 bottom
PR116  1M_5%_6  [R0603]  28.51 37.71 90 top
PR118  1M_5%_6  [R0603]  29.37 34.58 90 top
PR120  *100K_1%_6  [R0603]  26.22 51.24 270 top
PR126  *220_5%_8  [R0805]  21.91 29.02 90 bottom
PR184  *100K_5%_4  [R0402]  31.1 24.42 90 top
PR186  *100K_1%_2  [R0201]  32.19 26.28 90 top
PR191  1M_5%_6  [R0603]  118.83 33.84 0 top
PR204  316K_1%_4  [R0402]  135.06 27.29 180 top
PR205  *0_5%_2  [R0201]  135.98 28.76 270 top
PR206  100K_1%_4  [R0402]  132.71 27.7 270 top
PR207  100K_5%_4  [R0402]  136.46 29.75 0 top
PR208  *Short_0201  [S0201]  120.43 24.37 180 bottom
PR209  0.01_1%_0612  [RC3216]  111.57 27.01 90 bottom
PR210  *Short_0201  [S0201]  120.43 25.13 180 bottom
PR211  137K_1%_4  [R0402]  136.64 33.98 90 bottom
PR222  *215K_1%_4  [R0402]  25.61 23.74 180 top
PR224  *100K_1%_4  [R0402]  25.59 24.7 180 top
PR230  1M_5%_6  [R0603]  132.4 35.93 180 top
PR235  1M_5%_6  [R0603]  130.24 35.42 270 top
PR253  10K_1%_4  [R0402]  67.78 121.35 0 top
PR254  100_1%_4  [R0402]  67.63 122.67 270 bottom
PR256  2.2_5%_6  [R0603]  62.75 124.62 90 top
PR261  499K_1%_4  [R0402]  61.17 124.5 180 top
PR262  *Short_0603  [S0603]  65.52 116.06 0 top
PR263  6.04K_1%_4  [R0402]  67.78 122.31 180 top
PR265  *Short_0201  [S0201]  66.18 124.67 90 top
PR266  *0_5%_2  [R0201]  65.04 124.95 0 top
PR267  *Short_0201  [S0201]  62.37 123.94 90 bottom
PR268  73.2K_1%_4  [R0402]  120.58 35.42 90 bottom
PR269  SP@6.34K_1%_4  [R0402]  121.93 35.06 0 bottom
PR270  20K_1%_4  [R0402]  121.47 36.99 180 bottom
PR272  *Short_0201  [S0201]  121.32 39.05 0 bottom
PR273  *Short_0402  [S0402]  121.47 38.04 180 bottom
PR274  *Short_0201  [S0201]  121.32 41.18 0 bottom
PR275  100K_1%_2  [R0201]  119.75 41.39 90 bottom
PR276  *Short_0201  [S0201]  120.46 41.39 90 bottom
PR277  2.2_5%_6  [R0603]  117.03 40.37 180 top
PR283  15K_1%_4  [R0402]  158.28 26.35 270 top
PR284  *Short_0201  [S0201]  167.73 25.01 180 top
PR551  *2.2_5%_6  [R0603]  38.72 32.24 270 top
PR566  *Short_0201  [S0201]  38.03 27.55 180 top
PR567  10K_1%_4  [R0402]  41.11 25.92 270 top
PR568  20K_1%_4  [R0402]  40.14 25.92 270 top
PR569  *Short_0201  [S0201]  36.26 27.42 90 top
PR2060  *Short_0201  [S0201]  105.32 37.68 180 top
PR3020  150_5%_4  [R0402]  102.14 26.78 270 bottom
PR3021  29.4K_1%_4  [R0402]  108.47 27.85 90 bottom
PR3022  *Short_0201  [S0201]  108.39 25.77 270 bottom
PR6000  10_1%_6  [R0603]  146.72 35.29 90 bottom
PR6001  *4.7_5%_6  [R0603]  146.21 28.92 0 bottom
PR6002  *Short_0201  [S0201]  144.26 32.88 90 top
PR6003  10K_1%_4  [R0402]  144.33 38.21 180 bottom
PR6004  *Short_0201  [S0201]  143.04 34.05 90 bottom
PR6005  *Short_0201  [S0201]  143.04 33.06 90 bottom
PR6006  10K_1%_4  [R0402]  143.75 31.41 270 top
PR6007  100K_1%_4  [R0402]  144.08 39.23 0 bottom
PR6008  *Short_0201  [S0201]  159.24 36.61 90 bottom
PR6009  10K_1%_4  [R0402]  145.15 36.03 180 top
PR6010  *1K_1%_4  [R0402]  145.83 32.88 0 top
PR6011  1K_1%_4  [R0402]  146.57 35.34 90 top
PR6012  *100K_1%_4  [R0402]  142.38 31.48 0 top
PR6013  *Short_0402  [S0402]  154.34 27.49 270 bottom
PR6014  *10K_1%_4  [R0402]  146.7 31.41 270 top
PR6015  *Short_0201  [S0201]  156.4 28.87 90 bottom
PR6016  *Short_0201  [S0201]  152.36 27.95 0 bottom
PR6017  *Short_0603  [S0603]  145.2 36.28 270 bottom
PR6018  10_1%_6  [R0603]  41.08 19.04 180 top
PR6019  *4.7_5%_6  [R0603]  40.07 20.56 180 top
PR6020  *Short_0201  [S0201]  46.8 18.78 0 bottom
PR6021  10K_1%_4  [R0402]  47.53 14.34 180 bottom
PR6022  *Short_0201  [S0201]  46.04 16.88 270 bottom
PR6023  *Short_0201  [S0201]  27.21 27.6 0 top
PR6024  *100K_1%_4  [R0402]  44.15 15.86 0 top
PR6025  *Short_0603  [S0603]  42.48 15.99 90 top
PR6026  *Short_0201  [S0201]  39.56 13.7 180 bottom
PR6027  *Short_0402  [S0402]  27.47 26.63 0 top
PR6028  *Short_0201  [S0201]  27.21 28.56 180 top
PR6029  1K_1%_4  [R0402]  42.61 14.44 0 bottom
PR6030  *1K_1%_4  [R0402]  44.38 16.95 0 bottom
PR6031  *10K_1%_4  [R0402]  44.38 15.99 180 bottom
PR6414  *Short_0201  [S0201]  168.03 23.93 270 bottom
PR6416  100K_1%_2  [R0201]  168.72 25.26 180 top
PR6417  *Short_0402  [S0402]  166 18.55 180 top
PR6418  22.6K_1%_4  [R0402]  160.36 25.9 270 top
PR7000  2.2_5%_6  [R0603]  131.63 49.52 0 top
PR7001  100_1%_4  [R0402]  138.77 59.83 270 top
PR7002  *110_1%_4  [R0402]  139.74 59.83 270 top
PR7003  45.3_1%_4  [R0402]  140.7 60.08 270 top
PR7004  32.4K_1%_4  [R0402]  135.95 60.49 90 bottom
PR7005  39.2K_1%_4  [R0402]  141.54 57.85 0 top
PR7006  46.4K_1%_4  [R0402]  144.84 49.26 180 bottom
PR7007  100K_NTC_4_1%  [R0402]  131.56 61.53 0 bottom
PR7008  3.9_1%_4  [R0402]  143.62 56.2 270 top
PR7009  12.7K_1%_4  [R0402]  136.26 46.14 270 bottom
PR7010  12.7K_1%_4  [R0402]  131.18 55.74 90 top
PR7011  *10K_1%_2  [R0201]  137.25 61.2 90 bottom
PR7012  *Short_0201  [S0201]  137.96 61.33 90 bottom
PR7013  22.6K_1%_4  [R0402]  144.89 50.28 0 bottom
PR7014  2.32K_1%_4  [R0402]  143.01 50.28 0 bottom
PR7015  49.9_1%_4  [R0402]  140.83 60.09 90 bottom
PR7016  1.05K_1%_4  [R0402]  136.23 47.87 270 bottom
PR7017  1.05K_1%_4  [R0402]  133.16 55.15 180 top
PR7018  5.6M_1%_4  [R0402]  135.67 56.7 270 top
PR7019  10_1%_4  [R0402]  138.88 60.09 90 bottom
PR7020  *Short_0402  [S0402]  139.86 60.1 270 bottom
PR7021  100K_NTC_4_1%  [R0402]  123.48 80.73 0 bottom
PR7022  5.9K_1%_4  [R0402]  145.07 50.25 180 top
PR7023  12.7K_1%_4  [R0402]  145.05 49.29 180 top
PR7024  37.4K_1%_4  [R0402]  141.29 49.39 180 top
PR7025  *Short_0402  [S0402]  142.58 61.91 180 bottom
PR7026  5.6M_1%_4  [R0402]  135.77 49.59 270 bottom
PR7027  49.9_1%_4  [R0402]  143.06 50.25 0 top
PR7028  69.8_1%_4  [R0402]  143.04 49.29 0 top
PR7029  649_1%_4  [R0402]  139.56 49.26 0 top
PR7030  14K_1%_4  [R0402]  137.2 47.87 90 bottom
PR7031  14K_1%_4  [R0402]  133.54 53.81 90 top
PR7032  100K_NTC_4_1%  [R0402]  126.71 72.91 90 bottom
PR7033  10.5K_1%_4  [R0402]  137.22 46.14 90 bottom
PR7034  10.5K_1%_4  [R0402]  132.57 53.81 90 top
PR7035  3.16K_1%_4  [R0402]  140.45 51.68 180 top
PR7036  7.32K_1%_4  [R0402]  140.45 50.71 0 top
PR7037  10.5K_1%_4  [R0402]  137.81 49.26 0 top
PR7038  7.5K_1%_4  [R0402]  135.29 49.26 0 top
PR7039  *Short_0201  [S0201]  141.92 51.8 0 top
PR7040  301_1%_4  [R0402]  137.91 51.68 0 top
PR7041  100_1%_4  [R0402]  137.93 50.71 180 top
PR7042  *10K_1%_4  [R0402]  141.99 53.5 180 top
PR7043  100_1%_4  [R0402]  118.82 54.23 180 top
PR7044  *Short_0402  [S0402]  118.8 53.22 180 top
PR7045  100_1%_4  [R0402]  118.72 49.23 180 top
PR7046  *Short_0402  [S0402]  118.72 50.2 180 top
PR7047  10K_1%_4  [R0402]  142.94 46.85 90 bottom
PR7048  SP@63.4K_1%_4  [R0402]  143.04 49.26 0 bottom
PR7049  *10K_1%_4  [R0402]  144.38 47.28 0 bottom
PR7050  100_1%_4  [R0402]  101.53 79.39 270 top
PR7051  *Short_0402  [S0402]  102.93 79.11 180 top
PR7052  100_1%_4  [R0402]  101.53 77.66 90 top
PR7053  *Short_0402  [S0402]  102.93 78.14 180 top
PR7054  10K_1%_4  [R0402]  133.14 57.08 0 bottom
PR7055  26.1K_1%_4  [R0402]  132.68 58.43 270 bottom
PR7056  *10K_1%_4  [R0402]  133.15 55.14 180 bottom
PR7057  100_1%_4  [R0402]  115.58 43.55 0 top
PR7058  *Short_0402  [S0402]  117.51 43.78 180 top
PR7059  10K_1%_4  [R0402]  145.98 51.68 0 bottom
PR7060  107K_1%_4  [R0402]  144.26 55.97 90 bottom
PR7061  100_1%_4  [R0402]  115.58 45.96 0 top
PR7062  *Short_0402  [S0402]  117.49 45.45 180 top
PR7063  *10K_1%_4  [R0402]  144.33 54.22 0 top
PR7064  10_5%_6  [R0603]  135.72 54.4 90 top
PR7065  *SP@10K_1%_4  [R0402]  140.55 45.35 0 bottom
PR7066  SP@0_5%_4  [R0402]  140.55 47.69 270 bottom
PR7067  *Short_0201  [S0201]  141.92 59.5 270 bottom
PR7068  10K_1%_2  [R0201]  141.92 60.49 270 bottom
PR7069  *SP@10K_1%_4  [R0402]  141.67 47.69 270 bottom
PR7072  *2.2_5%_6  [R0603]  131.35 63.54 90 bottom
PR7073  *Short_0201  [S0201]  128.45 62.11 180 bottom
PR7074  *Short_0201  [S0201]  123.78 62.11 0 bottom
PR7075  *365_1%_4  [R0402]  138.16 47.87 270 bottom
PR7076  536_1%_4  [R0402]  138.19 46.14 270 bottom
PR7077  *Short_0402  [S0402]  133.11 51.24 0 bottom
PR7078  U42@1_5%_6  [R0603]  129.09 43.6 270 bottom
PR7079  *Short_0402  [S0402]  135.06 45.22 270 bottom
PR7080  U42@2.2_1%_6  [R0603]  135.04 47.41 270 bottom
PR7081  *U42@2.2_5%_6  [R0603]  131.38 53.91 270 bottom
PR7082  *Short_0201  [S0201]  128.41 54.98 180 bottom
PR7083  *Short_0201  [S0201]  123.76 54.98 0 bottom
PR7084  U42@536_1%_4  [R0402]  139.15 45.96 270 bottom
PR7085  *U42@365_1%_4  [R0402]  140.52 46.32 0 bottom
PR7087  *2.2_5%_6  [R0603]  136.33 43.62 0 bottom
PR7088  *Short_0201  [S0201]  132.01 38.87 180 bottom
PR7089  *Short_0201  [S0201]  127.37 38.87 0 bottom
PR7090  309_1%_4  [R0402]  142.81 59.07 270 bottom
PR7091  182_1%_4  [R0402]  142.17 59.1 180 top
PR7092  4.7K_1%_4  [R0402]  142.2 60.06 180 top
PR7093  4.7K_NTC_4_1%  [R0402]  133.16 43.55 0 bottom
PR7095  *2.2_5%_6  [R0603]  113.96 74.31 270 bottom
PR7096  *Short_0201  [S0201]  114.34 79.03 180 bottom
PR7097  *Short_0201  [S0201]  109.66 79.03 0 bottom
PR7098  649_1%_4  [R0402]  135.98 60.46 90 top
PR7099  715_1%_4  [R0402]  133.59 56.58 90 top
PR7100  4.75K_1%_4  [R0402]  132.6 56.57 270 top
PR7101  4.7K_NTC_4_1%  [R0402]  113.47 83.04 0 bottom
PR7102  *Short_0402  [S0402]  137.37 59.24 0 top
PR7103  *10K_1%_4  [R0402]  133.16 52.23 0 bottom
PR7104  10K_1%_4  [R0402]  133.16 53.2 180 bottom
PR7105  *Short_0402  [S0402]  118.96 68.19 180 top
PR7106  1_5%_6  [R0603]  123.99 72.63 225 bottom
PR7107  *Short_0402  [S0402]  116.9 70.04 90 bottom
PR7108  2.2_1%_6  [R0603]  115.66 69.48 90 bottom
PR7109  *Short_0402  [S0402]  125.73 79.27 135 bottom
PR7110  1_5%_6  [R0603]  125.97 74.56 45 bottom
PR7111  *Short_0402  [S0402]  130.11 76.24 0 bottom
PR7112  2.2_1%_6  [R0603]  130.9 78.12 270 bottom
PR7113  *Short_0402  [S0402]  139.91 43.29 90 bottom
PR7114  1_5%_6  [R0603]  140.78 39.69 0 bottom
PR7115  *Short_0402  [S0402]  143.44 41.44 90 bottom
PR7116  2.2_1%_6  [R0603]  142.99 44.92 180 bottom
PR9000  EV@1_5%_6  [R0603]  68.41 116.22 90 bottom
PR9001  EV@1_5%_6  [R0603]  76.26 108.95 180 bottom
PR9002  EV@499K_1%_4  [R0402]  68.92 113.8 0 top
PR9004  *EV@2.2_5%_6  [R0603]  77.53 117.97 180 top
PR9006  EV@1_5%_6  [R0603]  72.43 115.68 0 bottom
PR9008  *Short_0201  [S0201]  74.36 107.56 180 top
PR9009  EV@10K_1%_2  [R0201]  74.1 105.9 180 top
PR9011  EV@14.7K_1%_4  [R0402]  74.66 115.84 0 bottom
PR9012  *EV@1K_1%_4  [R0402]  75.25 117.08 180 top
PR9013  EV@10K_1%_4  [R0402]  73.09 106.51 90 top
PR9014  EV@1_5%_6  [R0603]  78.29 105.9 180 top
PR9015  *Short_0201  [S0201]  71.66 113.45 0 top
PR9016  *Short_0402  [S0402]  70.04 115.86 270 top
PR9017  *Short_0201  [S0201]  71.66 114.16 0 top
PR9018  *EV@12K_1%_4  [R0402]  71.31 115.76 270 top
PR9019  *EV@2.2_5%_6  [R0603]  83.25 108.44 270 top
PR9021  EV@20.5K_1%_4  [R0402]  71.69 112.18 180 bottom
PR9022  *EV@10K_1%_4  [R0402]  72.27 115.76 90 top
PR9023  EV@6.19K_1%_4  [R0402]  73.52 112.66 270 bottom
PR9024  EV@4.32K_1%_4  [R0402]  73.06 114.01 0 bottom
PR9025  *EV@0_5%_2  [R0201]  70.93 107.38 0 top
PR9026  EV@100_1%_4  [R0402]  70.22 108.22 0 top
PR9027  EV@16.5K_1%_4  [R0402]  70.24 113.73 270 bottom
PR9028  *Short_0201  [S0201]  69.66 109.08 0 top
PR9029  *Short_0201  [S0201]  69.53 111.82 180 top
PR9030  EV@309_1%_4  [R0402]  70.06 115.48 90 bottom
PR9031  EV@100_1%_4  [R0402]  68.9 112.84 180 top
PR9032  EV@14.7K_1%_4  [R0402]  74.33 108.6 90 bottom
PR9033  EV@10K_1%_2  [R0201]  71.44 110.37 180 bottom
PR9034  *Short_0201  [S0201]  77.58 111.07 0 top
PR9067  *Short_0805  [S0805]  21.65 101.08 45 top
PR9068  *Short_0805  [S0805]  25.72 97.01 180 top
PR9069  *Short_0402  [S0402]  23.18 87.87 270 top
PR9070  *Short_0402  [S0402]  24.19 87.87 90 top
PR9072  *Short_0402  [S0402]  22.16 87.87 270 top
PR9073  EV@5.6_5%_8  [R0805]  69.78 110.48 270 bottom
PR9074  EV@100K_1%_4  [R0402]  76.16 107.43 0 bottom
PR9075  EV@10K_1%_4  [R0402]  73.21 98.41 180 bottom
PR9076  EV@10K_1%_2  [R0201]  77.15 102.09 270 bottom
PR9077  EV@1M_5%_4  [R0402]  76.16 106.41 180 bottom
PR9078  *Short_0201  [S0201]  76.39 102.09 90 bottom
PR9079  *Short_0402  [S0402]  76.39 95.87 90 bottom
PR9080  EV@47_1%_4  [R0402]  74.36 95.87 90 bottom
PR9081  EV@133_1%_4  [R0402]  72.68 101.81 90 bottom
PR9082  EV@124_1%_4  [R0402]  73.34 99.81 270 bottom
PR9085  *Short_0402  [S0402]  74.23 115.43 90 top
PR9086  EV@100K_1%_4  [R0402]  140.07 63.49 90 bottom
PR9087  EV@10_5%_6  [R0603]  141.59 70.62 0 bottom
PR9088  EV@100K_1%_2  [R0201]  142.61 69.28 90 bottom
PR9089  EV@2.2_5%_6  [R0603]  139.56 71.36 90 bottom
PR9090  *Short_0201  [S0201]  141.9 69.28 90 bottom
PR9091  *EV@0_5%_2  [R0201]  140.85 67.93 180 top
PR9092  *EV@4.7_5%_6  [R0603]  133.69 69.05 0 bottom
PR9093  *Short_0201  [S0201]  141.84 67.88 0 top
PR9094  EV@6.49K_1%_4  [R0402]  141.46 63.89 0 bottom
PR9095  EV@2.2K_5%_4  [R0402]  141.87 66.99 180 bottom
PR9096  *EV@0_5%_4  [R0402]  141.95 66.03 0 bottom
PR9097  EV@9.31K_1%_4  [R0402]  141.49 62.88 180 bottom
PR9098  *Short_0402  [S0402]  139.86 65.9 270 top
PR9099  EV@22_5%_8  [R0805]  139.28 79.31 0 top
PR9100  EV@100K_1%_4  [R0402]  133.23 79.06 180 top
PR9101  EV@1M_5%_4  [R0402]  133.54 77.46 90 top
PR9102  EV@1M_5%_6  [R0603]  119.95 125.21 180 top
PR9103  EV@22_5%_8  [R0805]  120.33 120.38 180 top
PR9104  EV@1M_5%_6  [R0603]  119.95 123.79 0 top
PR9105  *EV@100K_1%_6  [R0603]  125.79 122.41 270 top
PR9227  22_5%_8  [R0805]  22.29 35.55 90 bottom
PR9244  *Short_0805  [S0805]  160.13 23.56 0 top
PR9245  *Short_0805  [S0805]  151.45 25.39 0 top
PR9248  *Short_0805  [S0805]  18.3 23.46 180 top
PR9249  *Short_0805  [S0805]  18.73 29.22 0 top
PR9251  *0_5%_2  [R0201]  30.67 26.28 270 top
PR9252  *0_5%_2  [R0201]  31.43 26.28 270 top
PR9253  *0_5%_4  [R0402]  35.49 22.85 90 top
PR9254  *0_1%_8  [R0805]  29.14 23.05 270 top
PR9255  100K_1%_2  [R0201]  42.18 26.66 90 top
PR9256  *Short_0201  [S0201]  42.18 27.67 90 top
PR9258  *Short_0201  [S0201]  110.45 43.93 0 bottom
PR9259  *short_2  [S0201]  111.01 33.26 90 top
PR9263  *Short_0201  [S0201]  140.7 77.71 0 top
PR9264  *2.2_5%_6  [R0603]  58 116.93 270 top
PR9265  100K_1%_4  [R0402]  62.52 125.28 180 bottom
PR9266  *Short_0201  [S0201]  49.26 121.91 180 top
PR9267  *Short_0805  [S0805]  70.04 119.39 270 top
PR9268  *0_5%_2  [R0201]  140.27 27.67 180 top
PR9269  *Short_0201  [S0201]  141.82 27.3 0 top
PR9270  *0_5%_2  [R0201]  47.05 11.42 0 top
PR9271  *Short_0201  [S0201]  47.05 10.65 0 top
PR9272  *0_5%_2  [R0201]  110.45 44.64 0 bottom
PR9273  *Short_0201  [S0201]  65.06 124.19 0 top
PR9274  100K_NTC_4_1%  [R0402]  72.02 109.54 180 bottom
PU1  BQ24780SRUYR  [QFN28-4X4-4-38P]  134.22 29.91 0 bottom
PU14  *G9661MF11U  [SOP8-6-1_27-9P-G5795F11U]  28.13 24.24 270 bottom
PU16  G5335QT2U  [QFN23-4X4-5-25P]  117.79 38.09 270 bottom
PU26  G5416QS1U  [QFN30-4X4-4-32P]  64.07 119.9 180 top
PU3002  TMP708AIDBVR  [SOT23-2_8-95-5P-LP2985-50DBVT]  105.9 26.76 0 bottom
PU3003  JW5222RSOTB_TRPBF  [SOT23-2_8-95-6P-1_1H]  162.16 23.25 0 bottom
PU3004  JW5213DFND_TRPBF  [DFN8-2X2-5-9P-MAX8902B]  41.24 29.5 90 top
PU6000  RT6256BGQUF  [QFN12-3X3-45-0_6H]  145.27 31.43 270 bottom
PU6001  JW7110DFNC_TRPBF  [DFN14-3X2-4-15P-0_85H]  154.85 26.73 180 top
PU6002  JW7110DFNC_TRPBF  [DFN14-3X2-4-15P-0_85H]  22.26 27.42 90 top
PU6003  RT6258CGQUF  [QFN12-3X3-45-0_6H]  44 20.05 90 bottom
PU7000  RT3602AJGQW  [QFN48-6X6-4-49P-EXC7900-SG11]  138.75 54.47 180 bottom
PU7001  U42@RT9610CGQW  [DFN8-2X2-5-9P]  133.11 47.99 180 bottom
PU7002  RT9610CGQW  [DFN8-2X2-5-9P]  118.71 69.12 0 bottom
PU7003  RT9610CGQW  [DFN8-2X2-5-9P]  128 77.53 180 bottom
PU7004  RT9610CGQW  [DFN8-2X2-5-9P]  141.62 42.3 180 bottom
PU9000  EV@RT8813DGQW  [QFN24-4X4-5-25P-RT8813D]  73.98 110.78 180 top
PU9002  EV@JW7110DFNC_TRPBF  [DFN14-3X2-4-15P-0_85H]  22.54 93.59 0 top
PU9003  EV@G9336ADJTP1U  [TSOT23-6-2_8-95-6P-1H]  75.88 99.17 90 bottom
PU9004  EV@G5335QT2U  [QFN23-4X4-5-25P]  137.81 66.69 270 bottom
Q3  2N7002KDW  [SOT363-2_1-65-6P]  67.7 17.51 180 top
Q9  EV@PJA138K  [SOT23-2-95-3P]  84.9 91.68 270 bottom
Q13  EV@PJT138K  [SC70-2_1-65-6P]  173.29 31.74 180 top
Q14  EV@DMG1012T-7  [SOT23-1_38-5-3P]  87.69 95.24 0 top
Q15  *EV@DMG1012T-7  [SOT23-1_38-5-3P]  98.36 123.94 180 top
Q16  EV@DMG1012T-7  [SOT23-1_38-5-3P]  87.69 92.95 0 top
Q20  EV@DMG1012T-7  [SOT23-1_38-5-3P]  136.21 101.08 0 top
Q21  *PJA138K  [SOT23-2-95-3P]  200.21 20.43 180 bottom
Q22  2N7002KTB  [SOT23-1_38-5-3P]  52 24.27 0 top
Q27  2N7002KDW  [SOT363-2_1-65-6P]  72.43 16.55 180 top
Q29  *BSS138BK  [SOT23-2_38-95-3P]  81.47 22.87 90 bottom
Q30  KBL@DMP2130L-7  [SOT23-2_38-95-3P]  196.18 14.62 90 bottom
Q31  KBL@DDTC144EUA-7-F  [SOT23-1_7-65-3P]  197.05 21.17 180 bottom
Q32  PBA@DMP2130L-7  [SOT23-2_38-95-3P]  50.18 19.42 90 top
Q33  *2N7002KTB  [SOT23-1_38-5-3P]  180.58 17.64 0 bottom
Q34  SSD@2N7002K  [SOT23-2-95-3P]  24.95 8.24 180 top
Q41  HDMI_N@SSM6N43FU  [SC70-2_1-65-6P]  24.32 63.49 90 top
Q63  2N7002KTB  [SOT23-1_38-5-3P]  174.18 21.04 0 top
Q81  PJA138K  [SOT23-2-95-3P]  24.01 40.37 180 top
Q85  DMG301NU-7  [SOT23-2-95-3P]  140.9 33.18 90 top
Q86  METR3904-G  [SOT23-2-95-3P]  143.78 38.31 180 top
Q6505  TPC@2N7002K  [SOT23-2-95-3P]  8.82 23.1 0 bottom
Q6507  HDMI_N@2N7002K  [SOT23-2-95-3P]  18.1 87.62 270 top
Q6508  AP2331SA-7  [SOT23-2-95-3P]  19.24 81.9 180 bottom
Q6509  2N7002K  [SOT23-2-95-3P]  172.27 17.51 180 top
Q6512  EV@2N7002KTB  [SOT23-1_38-5-3P]  201.69 11.21 180 top
Q6515  TPC@2N7002K  [SOT23-2-95-3P]  12.79 6.59 270 top
Q6516  TPC@EMB20P03V  [POWER-3X3-65-5P]  17.94 14.34 180 top
Q6518  TPC@MMBT3906-7-F  [SOT23-2-95-3P]  16.32 8.14 90 top
Q6519  TPC@2N7002KDW  [SOT363-2_1-65-6P]  21.22 15.35 270 top
Q6520  *2N7002KTB  [SOT23-1_38-5-3P]  52 26.48 0 top
Q6521  2N7002KDW  [SOT363-2_1-65-6P]  56.58 102.48 270 top
Q6522  DDTC144EUA-7-F  [SOT23-1_7-65-3P]  55.56 109.59 0 top
Q6523  METR3904-G  [SOT23-2-95-3P]  176.92 31.02 180 top
Q6531  2N7002K  [SOT23-2-95-3P]  59.5 99.55 0 top
Q6533  HDMI_N@DMN601K-7  [SOT23-2-95-3P]  21.68 74.56 0 bottom
R1  100K_5%_4  [R0402]  94.04 28.46 0 bottom
R2  24.9_1%_4  [R0402]  101.28 62.85 0 bottom
R3  *Short_0201  [S0201]  100.75 72.02 270 top
R4  *Short_0201  [S0201]  102.63 70.9 270 top
R5  *Short_0201  [S0201]  102.68 76.31 270 top
R6  *Short_0201  [S0201]  103.67 69.25 270 top
R7  *Short_0201  [S0201]  102.22 73.19 180 top
R9  499_1%_2  [R0201]  103.44 72.25 180 bottom
R10  49.9_1%_2  [R0201]  100.65 67.3 180 bottom
R11  *1K_5%_2  [R0201]  104.96 73.52 180 top
R12  51_5%_2  [R0201]  103.82 76.63 180 top
R13  51_5%_2  [R0201]  100.75 72.76 180 bottom
